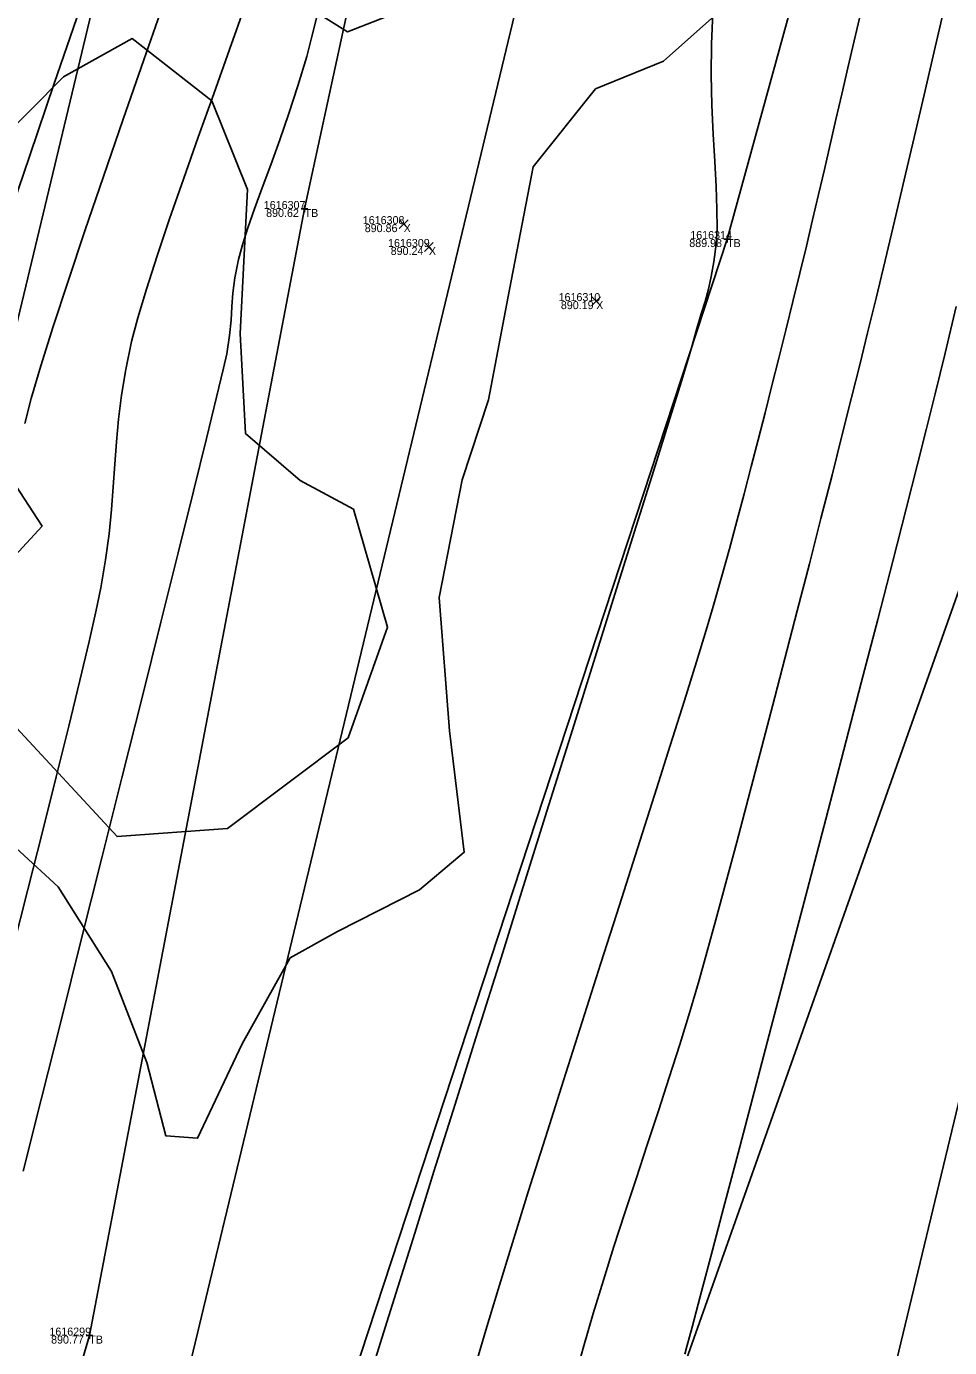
# Model space of a CAD drawing. Extents: x 1957117 to 1971063, y 701601 to 715861.
# Drawn here: x 1963385.1 to 1963425.5, y 706329.7 to 706387.5 of the extents above; entities that cross this region are included whole.
import ezdxf

# ---------------------------------------------------------------- set-up
doc = ezdxf.new("R2010")
doc.units = 0
for name, color, linetype in [('AP_X_Lights', 7, 'Continuous'), ('DT_X_Break_Line', 7, 'Continuous'), ('DT_X_Contour_Major', 7, 'Continuous'), ('DT_X_Contour_Minor', 7, 'Continuous'), ('DT_X_TIN_Hull', 7, 'Continuous'), ('GE_X_CL_20', 7, 'Continuous'), ('HY_X_Water_Edge', 7, 'Continuous'), ('PV_P_Drive', 7, 'Continuous'), ('PV_P_Shoulder', 7, 'Continuous'), ('RS_Raster1', 7, 'Continuous'), ('RW_X_Esmt_RR', 7, 'Continuous'), ('SC_Scratch1', 7, 'Continuous'), ('SC_Shading5', 7, 'Continuous'), ('VG_X_Tree_Line_Rt', 7, 'Continuous')]:
    doc.layers.add(name, color=color, linetype=linetype)

msp = doc.modelspace()

# ---------------------------------------------------------------- linework, layer by layer
at = {"layer": 'AP_X_Lights'}
for p, q in [((1963401.401, 706378.643), (1963401.789, 706379.033)), ((1963401.401, 706379.033), (1963401.789, 706378.643)), ((1963402.506, 706377.644), (1963402.894, 706378.034)), ((1963402.506, 706378.034), (1963402.894, 706377.644)), ((1963409.82, 706375.275), (1963410.208, 706375.665)), ((1963409.82, 706375.665), (1963410.208, 706375.275))]:
    msp.add_line(p, q, dxfattribs=at)
at = {"layer": 'DT_X_Break_Line'}
for points in [[(1963248.355, 705747.376), (1963261.829, 705795.923), (1963267.581, 705840.559), (1963287.153, 705892.264), (1963291.083, 705944.763), (1963301.574, 705996.211), (1963311.528, 706039.027), (1963334.717, 706086.75), (1963331.957, 706106.508), (1963348.786, 706182.796), (1963365.664, 706223.934), (1963373.462, 706281.461), (1963387.853, 706330.217), (1963397.264, 706379.501), (1963407.696, 706427.592), (1963426.755, 706477.16), (1963442.136, 706524.014), (1963446.007, 706569.971), (1963489.391, 706666.839), (1963500.526, 706701.536)], [(1963509.92, 706697.686), (1963502.832, 706666.547), (1963464.625, 706568.104), (1963439.113, 706472.593), (1963428.782, 706425.675), (1963415.739, 706378.185), (1963398.991, 706327.191), (1963392.393, 706279.173), (1963377.9, 706227.719), (1963369.87, 706175.335), (1963345.874, 706098.69), (1963341.112, 706081.071), (1963328.328, 706036.261), (1963311.276, 705989.111), (1963300.503, 705940.076), (1963293.199, 705890.767), (1963276.592, 705844.792), (1963268.336, 705791.927), (1963260.722, 705745.719)], [(1963274.602, 705735.973), (1963292.982, 705784.032), (1963302.841, 705839.645), (1963309.732, 705887.345), (1963317.684, 705934.969), (1963334.587, 705978.262), (1963333.365, 706039.768), (1963361.138, 706084.843), (1963357.365, 706105.535), (1963378.943, 706178.629), (1963396.437, 706235.152), (1963403.946, 706276.884), (1963413.88, 706328.936), (1963427.392, 706367.127), (1963440.399, 706419.945), (1963448.239, 706464.72), (1963530.121, 706695.075)]]:
    msp.add_lwpolyline(points, dxfattribs=at)
at = {"layer": 'DT_X_Contour_Major'}
for points in [[(1963397.866, 706388.199), (1963397.573, 706386.992), (1963397.356, 706386.168), (1963396.973, 706384.889), (1963396.576, 706383.671), (1963396.177, 706382.519), (1963395.787, 706381.438), (1963395.417, 706380.433), (1963395.079, 706379.51), (1963394.785, 706378.674), (1963394.546, 706377.93), (1963394.373, 706377.284), (1963394.217, 706376.483), (1963394.133, 706375.822), (1963394.09, 706375.231), (1963394.052, 706374.638), (1963393.986, 706373.973), (1963393.859, 706373.163), (1963393.719, 706372.536), (1963393.416, 706371.275), (1963392.972, 706369.456), (1963392.404, 706367.157), (1963391.733, 706364.454), (1963390.978, 706361.422), (1963390.158, 706358.138), (1963389.292, 706354.678), (1963388.4, 706351.119), (1963387.501, 706347.536), (1963386.615, 706344.007), (1963385.76, 706340.607), (1963384.957, 706337.413)], [(1963397.866, 706388.199), (1963397.573, 706386.992), (1963397.356, 706386.168), (1963396.973, 706384.889), (1963396.576, 706383.671), (1963396.177, 706382.519), (1963395.787, 706381.438), (1963395.417, 706380.433), (1963395.079, 706379.51), (1963394.785, 706378.674), (1963394.546, 706377.93), (1963394.373, 706377.284), (1963394.217, 706376.483), (1963394.133, 706375.822), (1963394.09, 706375.231), (1963394.052, 706374.638), (1963393.986, 706373.973), (1963393.859, 706373.163), (1963393.719, 706372.536), (1963393.416, 706371.275), (1963392.972, 706369.456), (1963392.404, 706367.157), (1963391.733, 706364.454), (1963390.978, 706361.422), (1963390.158, 706358.138), (1963389.292, 706354.678), (1963388.4, 706351.119), (1963387.501, 706347.536), (1963386.615, 706344.007), (1963385.76, 706340.607), (1963384.957, 706337.413)], [(1963415.11, 706388.084), (1963415.052, 706386.722), (1963415.046, 706385.369), (1963415.078, 706384.047), (1963415.134, 706382.776), (1963415.198, 706381.579), (1963415.258, 706380.478), (1963415.298, 706379.493), (1963415.305, 706378.646), (1963415.264, 706377.96), (1963415.161, 706377.188), (1963415.047, 706376.548), (1963414.92, 706375.99), (1963414.776, 706375.46), (1963414.611, 706374.907), (1963414.423, 706374.279), (1963414.208, 706373.524), (1963414.033, 706372.933), (1963413.682, 706371.785), (1963413.174, 706370.144), (1963412.53, 706368.072), (1963411.768, 706365.631), (1963410.91, 706362.884), (1963409.974, 706359.894), (1963408.981, 706356.723), (1963407.95, 706353.432), (1963406.902, 706350.086), (1963405.855, 706346.746), (1963404.829, 706343.475), (1963403.845, 706340.335), (1963402.922, 706337.389), (1963402.08, 706334.7), (1963401.339, 706332.329), (1963400.719, 706330.339), (1963400.238, 706328.794)], [(1963415.11, 706388.084), (1963415.052, 706386.722), (1963415.046, 706385.369), (1963415.078, 706384.047), (1963415.134, 706382.776), (1963415.198, 706381.579), (1963415.258, 706380.478), (1963415.298, 706379.493), (1963415.305, 706378.646), (1963415.264, 706377.96), (1963415.161, 706377.188), (1963415.047, 706376.548), (1963414.92, 706375.99), (1963414.776, 706375.46), (1963414.611, 706374.907), (1963414.423, 706374.279), (1963414.208, 706373.524), (1963414.033, 706372.933), (1963413.682, 706371.785), (1963413.174, 706370.144), (1963412.53, 706368.072), (1963411.768, 706365.631), (1963410.91, 706362.884), (1963409.974, 706359.894), (1963408.981, 706356.723), (1963407.95, 706353.432), (1963406.902, 706350.086), (1963405.855, 706346.746), (1963404.829, 706343.475), (1963403.845, 706340.335), (1963402.922, 706337.389), (1963402.08, 706334.7), (1963401.339, 706332.329), (1963400.719, 706330.339), (1963400.238, 706328.794)]]:
    msp.add_lwpolyline(points, dxfattribs=at)
at = {"layer": 'DT_X_Contour_Minor'}
for points in [[(1963394.669, 706388.404), (1963393.981, 706386.472), (1963393.29, 706384.54), (1963392.612, 706382.639), (1963391.963, 706380.803), (1963391.358, 706379.063), (1963390.813, 706377.45), (1963390.345, 706375.998), (1963389.969, 706374.737), (1963389.702, 706373.701), (1963389.45, 706372.48), (1963389.266, 706371.357), (1963389.135, 706370.309), (1963389.041, 706369.308), (1963388.967, 706368.331), (1963388.899, 706367.353), (1963388.82, 706366.348), (1963388.714, 706365.292), (1963388.565, 706364.159), (1963388.358, 706362.925), (1963388.157, 706361.95), (1963387.846, 706360.581), (1963387.441, 706358.874), (1963386.956, 706356.881), (1963386.406, 706354.656), (1963385.804, 706352.254), (1963385.167, 706349.728), (1963384.507, 706347.131)], [(1963394.669, 706388.404), (1963393.981, 706386.472), (1963393.29, 706384.54), (1963392.612, 706382.639), (1963391.963, 706380.803), (1963391.358, 706379.063), (1963390.813, 706377.45), (1963390.345, 706375.998), (1963389.969, 706374.737), (1963389.702, 706373.701), (1963389.45, 706372.48), (1963389.266, 706371.357), (1963389.135, 706370.309), (1963389.041, 706369.308), (1963388.967, 706368.331), (1963388.899, 706367.353), (1963388.82, 706366.348), (1963388.714, 706365.292), (1963388.565, 706364.159), (1963388.358, 706362.925), (1963388.157, 706361.95), (1963387.846, 706360.581), (1963387.441, 706358.874), (1963386.956, 706356.881), (1963386.406, 706354.656), (1963385.804, 706352.254), (1963385.167, 706349.728), (1963384.507, 706347.131)], [(1963391.158, 706388.672), (1963390.234, 706386.028), (1963389.332, 706383.432), (1963388.469, 706380.926), (1963387.66, 706378.551), (1963386.923, 706376.35), (1963386.275, 706374.364), (1963385.732, 706372.636), (1963385.312, 706371.207), (1963385.031, 706370.119)], [(1963391.158, 706388.672), (1963390.234, 706386.028), (1963389.332, 706383.432), (1963388.469, 706380.926), (1963387.66, 706378.551), (1963386.923, 706376.35), (1963386.275, 706374.364), (1963385.732, 706372.636), (1963385.312, 706371.207), (1963385.031, 706370.119)], [(1963409.089, 706328.375), (1963409.471, 706329.767), (1963409.887, 706331.191), (1963410.33, 706332.641), (1963410.794, 706334.109), (1963411.273, 706335.591), (1963411.76, 706337.078), (1963412.25, 706338.565), (1963412.735, 706340.044), (1963413.211, 706341.51), (1963413.67, 706342.956), (1963414.107, 706344.375), (1963414.515, 706345.761), (1963414.857, 706346.974), (1963415.251, 706348.406), (1963415.689, 706350.025), (1963416.164, 706351.799), (1963416.667, 706353.699), (1963417.191, 706355.691), (1963417.728, 706357.746), (1963418.269, 706359.832), (1963418.808, 706361.918), (1963419.336, 706363.972), (1963419.846, 706365.964), (1963420.329, 706367.861), (1963420.778, 706369.634), (1963421.184, 706371.251), (1963421.541, 706372.68), (1963421.884, 706374.077), (1963422.254, 706375.604), (1963422.647, 706377.243), (1963423.057, 706378.972), (1963423.482, 706380.771), (1963423.915, 706382.621), (1963424.355, 706384.5), (1963424.795, 706386.389), (1963425.232, 706388.268)], [(1963409.089, 706328.375), (1963409.471, 706329.767), (1963409.887, 706331.191), (1963410.33, 706332.641), (1963410.794, 706334.109), (1963411.273, 706335.591), (1963411.76, 706337.078), (1963412.25, 706338.565), (1963412.735, 706340.044), (1963413.211, 706341.51), (1963413.67, 706342.956), (1963414.107, 706344.375), (1963414.515, 706345.761), (1963414.857, 706346.974), (1963415.251, 706348.406), (1963415.689, 706350.025), (1963416.164, 706351.799), (1963416.667, 706353.699), (1963417.191, 706355.691), (1963417.728, 706357.746), (1963418.269, 706359.832), (1963418.808, 706361.918), (1963419.336, 706363.972), (1963419.846, 706365.964), (1963420.329, 706367.861), (1963420.778, 706369.634), (1963421.184, 706371.251), (1963421.541, 706372.68), (1963421.884, 706374.077), (1963422.254, 706375.604), (1963422.647, 706377.243), (1963423.057, 706378.972), (1963423.482, 706380.771), (1963423.915, 706382.621), (1963424.355, 706384.5), (1963424.795, 706386.389), (1963425.232, 706388.268)], [(1963387.432, 706388.244), (1963386.317, 706384.99), (1963385.244, 706381.839), (1963384.23, 706378.837)], [(1963387.432, 706388.244), (1963386.317, 706384.99), (1963385.244, 706381.839), (1963384.23, 706378.837)], [(1963404.752, 706328.974), (1963405.188, 706330.46), (1963405.727, 706332.24), (1963406.352, 706334.268), (1963407.048, 706336.499), (1963407.799, 706338.884), (1963408.588, 706341.379), (1963409.401, 706343.936), (1963410.221, 706346.509), (1963411.032, 706349.053), (1963411.818, 706351.519), (1963412.564, 706353.863), (1963413.254, 706356.037), (1963413.872, 706357.995), (1963414.401, 706359.692), (1963414.827, 706361.079), (1963415.132, 706362.112), (1963415.494, 706363.39), (1963415.839, 706364.634), (1963416.17, 706365.851), (1963416.489, 706367.047), (1963416.798, 706368.231), (1963417.101, 706369.408), (1963417.401, 706370.587), (1963417.699, 706371.774), (1963417.999, 706372.976), (1963418.304, 706374.201), (1963418.615, 706375.456), (1963418.92, 706376.696), (1963419.207, 706377.881), (1963419.48, 706379.024), (1963419.741, 706380.136), (1963419.996, 706381.23), (1963420.248, 706382.318), (1963420.5, 706383.412), (1963420.758, 706384.525), (1963421.023, 706385.67), (1963421.301, 706386.857), (1963421.594, 706388.1)], [(1963404.752, 706328.974), (1963405.188, 706330.46), (1963405.727, 706332.24), (1963406.352, 706334.268), (1963407.048, 706336.499), (1963407.799, 706338.884), (1963408.588, 706341.379), (1963409.401, 706343.936), (1963410.221, 706346.509), (1963411.032, 706349.053), (1963411.818, 706351.519), (1963412.564, 706353.863), (1963413.254, 706356.037), (1963413.872, 706357.995), (1963414.401, 706359.692), (1963414.827, 706361.079), (1963415.132, 706362.112), (1963415.494, 706363.39), (1963415.839, 706364.634), (1963416.17, 706365.851), (1963416.489, 706367.047), (1963416.798, 706368.231), (1963417.101, 706369.408), (1963417.401, 706370.587), (1963417.699, 706371.774), (1963417.999, 706372.976), (1963418.304, 706374.201), (1963418.615, 706375.456), (1963418.92, 706376.696), (1963419.207, 706377.881), (1963419.48, 706379.024), (1963419.741, 706380.136), (1963419.996, 706381.23), (1963420.248, 706382.318), (1963420.5, 706383.412), (1963420.758, 706384.525), (1963421.023, 706385.67), (1963421.301, 706386.857), (1963421.594, 706388.1)], [(1963425.757, 706375.231), (1963425.27, 706373.2), (1963424.837, 706371.411), (1963424.466, 706369.903), (1963424.073, 706368.336), (1963423.575, 706366.382), (1963422.987, 706364.098), (1963422.326, 706361.542), (1963421.607, 706358.771), (1963420.844, 706355.843), (1963420.053, 706352.815), (1963419.25, 706349.746), (1963418.449, 706346.692), (1963417.667, 706343.712), (1963416.918, 706340.862), (1963416.218, 706338.2), (1963415.581, 706335.785), (1963415.025, 706333.673), (1963414.562, 706331.922), (1963414.21, 706330.589), (1963413.984, 706329.733), (1963413.898, 706329.41)], [(1963425.757, 706375.231), (1963425.27, 706373.2), (1963424.837, 706371.411), (1963424.466, 706369.903), (1963424.073, 706368.336), (1963423.575, 706366.382), (1963422.987, 706364.098), (1963422.326, 706361.542), (1963421.607, 706358.771), (1963420.844, 706355.843), (1963420.053, 706352.815), (1963419.25, 706349.746), (1963418.449, 706346.692), (1963417.667, 706343.712), (1963416.918, 706340.862), (1963416.218, 706338.2), (1963415.581, 706335.785), (1963415.025, 706333.673), (1963414.562, 706331.922), (1963414.21, 706330.589), (1963413.984, 706329.733), (1963413.898, 706329.41)]]:
    msp.add_lwpolyline(points, dxfattribs=at)
at = {"layer": 'DT_X_TIN_Hull'}
msp.add_lwpolyline([(1963309.732, 705887.345), (1963335.126, 705936.766), (1963334.587, 705978.262), (1963361.138, 706084.843), (1963378.943, 706178.629), (1963396.437, 706235.152), (1963403.946, 706276.884), (1963413.88, 706328.936), (1963427.392, 706367.127), (1963440.399, 706419.945), (1963448.239, 706464.72), (1963464.625, 706568.104)], dxfattribs=at)
at = {"layer": 'GE_X_CL_20'}
msp.add_lwpolyline([(1963418.3, 706437.397), (1962895.621, 704261.062)], dxfattribs=at)
at = {"layer": 'HY_X_Water_Edge'}
msp.add_spline([(1963191.723, 701994.048), (1963062.047, 702441.167), (1962863.491, 703169.356), (1962827.53, 703438.691), (1962823.213, 703537.412), (1962817.962, 703593.874), (1962817.97, 703697.316), (1962828.582, 703804.235), (1962836.461, 703844.734), (1962850.687, 703896.004), (1962867.251, 703938.846), (1962873.848, 703992.355), (1962884.135, 704091.371), (1962891.241, 704140.854), (1962897.382, 704180.529), (1962905.467, 704230.979), (1962943.949, 704328.022), (1962948.537, 704378.842), (1962964.114, 704426.264), (1963004.885, 704570.73), (1963042.054, 704716.522), (1963062.038, 704814.417), (1963072.171, 704860.237), (1963090.023, 704956.798), (1963107.066, 705031.783), (1963133.773, 705105.742), (1963148.685, 705206.74), (1963175.48, 705301.059), (1963191.635, 705353.417), (1963210.988, 705447.286), (1963219.532, 705497.27), (1963230.124, 705549.475), (1963251.052, 705591.159), (1963275.289, 705693.429), (1963292.982, 705784.032), (1963302.841, 705839.645), (1963335.126, 705936.766), (1963359.752, 706046.75), (1963389.133, 706177.299), (1963417.827, 706273.456), (1963475.868, 706451.902), (1963533.782, 706640.53), (1963553.86, 706696.984), (1963580.184, 706715.425), (1963609.172, 706718.73), (1963617.062, 706714.691), (1963619.447, 706694.678), (1963564.282, 706533.07), (1963531.853, 706395.229), (1963434.4, 706006.96), (1963354.09, 705679.186), (1963237.513, 705206.07), (1963167.369, 704892.962), (1963059.145, 704434.176), (1962907.914, 703908.742), (1962877.458, 703703.326), (1962898.357, 703412.121), (1962942.65, 703052.267), (1963048.963, 702674.866), (1963191.468, 702189.666), (1963245.396, 702019.832)], degree=3, dxfattribs=at)
at = {"layer": 'PV_P_Drive'}
for p, q in [((1963397.264, 706379.647), (1963397.264, 706379.355)), ((1963397.118, 706379.501), (1963397.41, 706379.501)), ((1963397.264, 706379.501), (1963397.264, 706379.501)), ((1963415.593, 706378.185), (1963415.885, 706378.185)), ((1963415.739, 706378.331), (1963415.739, 706378.039)), ((1963415.739, 706378.185), (1963415.739, 706378.185)), ((1963387.707, 706330.217), (1963387.999, 706330.217)), ((1963387.853, 706330.363), (1963387.853, 706330.071)), ((1963387.853, 706330.217), (1963387.853, 706330.217))]:
    msp.add_line(p, q, dxfattribs=at)
at = {"layer": 'RW_X_Esmt_RR'}
msp.add_line((1962924.791, 704254.057), (1963447.47, 706430.392), dxfattribs=at)
msp.add_lwpolyline([(1962866.45, 704268.068), (1963123.345, 705337.727), (1963135.496, 705336.937), (1963400.797, 706441.601)], dxfattribs=at)
at = {"layer": 'SC_Shading5'}
for points in [[(1963026.912, 704294.121), (1963138.818, 704737.794), (1963251.679, 705213.963), (1963374.306, 705730.111), (1963454.783, 706045.593), (1963517.244, 706296.713), (1963562.763, 706479.256), (1963580.13, 706553.799), (1963589.678, 706586.994)], [(1963609.915, 706579.703), (1963587.283, 706499.153), (1963552.056, 706354.005), (1963480.911, 706069.234), (1963357.401, 705576.869), (1963272.751, 705226.931), (1963210.247, 704956.481), (1963044.97, 704288.881)]]:
    msp.add_spline(points, degree=3, dxfattribs=at)
at = {"layer": 'VG_X_Tree_Line_Rt'}
for points in [[(1963381.767, 706386.932), (1963378.443, 706384.822), (1963381.767, 706386.932), (1963384.207, 706388.748), (1963382.044, 706390.553), (1963380.299, 706393.272), (1963387.032, 706393.185), (1963393.305, 706391.374), (1963395.066, 706389.812), (1963399.138, 706387.246), (1963404.04, 706389.179), (1963404.468, 706394.346), (1963403.29, 706401.854), (1963401.185, 706407.689), (1963398.895, 706412.377), (1963401.95, 706414.045)], [(1963417.174, 706389.735), (1963412.957, 706385.973), (1963409.99, 706384.751), (1963407.258, 706381.342), (1963406.221, 706375.986), (1963405.302, 706371.158), (1963404.157, 706367.648), (1963403.15, 706362.504), (1963403.606, 706356.67), (1963404.244, 706351.362), (1963402.29, 706349.713), (1963398.703, 706347.893), (1963396.632, 706346.736), (1963394.539, 706342.979), (1963392.583, 706338.848), (1963391.199, 706338.953), (1963390.366, 706342.166), (1963388.827, 706346.142), (1963386.486, 706349.848), (1963383.128, 706352.939)], [(1963383.543, 706357.997), (1963389.068, 706352.05), (1963393.895, 706352.401), (1963399.171, 706356.371), (1963400.895, 706361.214), (1963399.407, 706366.364), (1963397.078, 706367.621), (1963394.687, 706369.676), (1963394.448, 706374.059), (1963394.766, 706380.347), (1963393.202, 706384.239), (1963389.721, 706386.952), (1963386.727, 706385.288), (1963383.787, 706382.336)], [(1963383.476, 706369.175), (1963385.786, 706365.626), (1963383.378, 706363.035)]]:
    msp.add_lwpolyline(points, dxfattribs=at)

# ---------------------------------------------------------------- texts
at = {"layer": 'PV_P_Shoulder'}
for s, p in [('890.62', (1963395.583, 706379.151)), ('890.86', (1963399.895, 706378.488)), ('889.98', (1963414.086, 706377.835)), ('890.24', (1963401.03, 706377.489)), ('890.19', (1963408.471, 706375.12)), ('890.77', (1963386.18, 706329.867))]:
    msp.add_text(s, height=0.35, dxfattribs=at).set_placement(p)
at = {"layer": 'RS_Raster1'}
for s, p in [('1616307', (1963395.481, 706379.501)), ('1616308', (1963399.81, 706378.838)), ('1616314', (1963414.13, 706378.185)), ('1616309', (1963400.915, 706377.839)), ('1616310', (1963408.372, 706375.47)), ('1616299', (1963386.106, 706330.217))]:
    msp.add_text(s, height=0.35, dxfattribs=at).set_placement(p)
at = {"layer": 'SC_Scratch1'}
for s, p in [('TB', (1963397.264, 706379.151)), ('X', (1963401.595, 706378.488)), ('TB', (1963415.739, 706377.835)), ('X', (1963402.7, 706377.489)), ('X', (1963410.014, 706375.12)), ('TB', (1963387.853, 706329.867))]:
    msp.add_text(s, height=0.35, dxfattribs=at).set_placement(p)

doc.saveas('drawing.dxf')
